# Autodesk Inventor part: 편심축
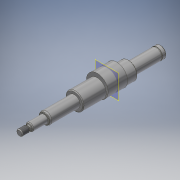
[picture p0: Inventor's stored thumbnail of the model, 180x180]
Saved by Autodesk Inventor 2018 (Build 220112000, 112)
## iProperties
Created: 2015-09
Part Number: 편심축
Material: 강철, 연강
Document SubType Name: Modeling
Designer: mduedu
Density: 1 g/cm^3
Appearance: 강철
Author: mduedu
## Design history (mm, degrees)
sketch "스케치1"
  geometry: L1 (-91, 0)-(91, 0); L2 (-91, 0)-(-91, 7.5); L3 (-91, 7.5)-(-49.85, 7.5); L4 (-49.85, 7.5)-(-49.85, 11.5); L5 (-49.85, 11.5)-(20.15, 11.5); L6 (20.15, 11.5)-(20.15, 7.5); L7 (20.15, 7.5)-(59.15, 7.5); L8 (59.15, 7.5)-(59.15, 5); L9 (59.15, 5)-(78.15, 5); L10 (78.15, 5)-(78.15, 3); L11 (78.15, 3)-(80.15, 3); L12 (81.882, 4)-(91, 4); L13 (91, 4)-(91, 0); L14 (80.15, 3)-(81.882, 4); 2 further points
  constraints: 28 end point, 9 parallel, 2 perpendicular, 1 coincident, 1 collinear, 1 horizontal, 1 midpoint
  dimensions: "d0" = 41.15 distance of L2.end L3.end; "d2" = 70 distance of L4.end L5.end; "d3" = 39 distance of L6.end L7.end; "d4" = 182 distance of L1.start L1.end; "d5" = 19 distance of L8.end L9.end; "d7" = 8 diameter of L12 L1; "d8" = 6 diameter of L11 L1; "d9" = 10 diameter of L9 L1; "d10" = 15 diameter of L7 L1; "d11" = 23 diameter of L5 L1; "d12" = 15 diameter of L3 L1; "d40" = 30 deg angle of L14 L12; "d41" = 2 distance of L10.end L11.end; "d42" = 3.73205 horizontal distance of L12.start L10.end (derived)
revolve "회전1" sketch "스케치1" stored, may be unused: angle "d13" = 90 deg
fillet "모깎기1" dims "d43" = 0.6
sketch "스케치2"
  geometry: L1 (-91, 7.5)-(-49.85, 7.5) reference; L2 (-91, -7.5)-(-91, 7.5) reference; L3 (91, -4)-(91, 4) reference; L4 (-91, 0)-(91, 0); L5 (-86, 7.5)-(-84.85, 7.5); L6 (-84.85, 7.5)-(-84.85, 7.15); L7 (-84.85, 7.15)-(-86, 7.15); L8 (-86, 7.15)-(-86, 7.5); 1 further point
  constraints: 10 end point, 2 midpoint, 2 parallel, 1 horizontal, 1 perpendicular, 1 point on line
  dimensions: "d14" = 5 distance between parallel lines of L8 L2; "d15" = 14.3 diameter of L7 L4; "d16" = 1.15 distance of L6.end L7.end
revolve "회전2" sketch "스케치2" stored, may be unused: angle "d17" = 90 deg
node "작업 평면1"
sketch "스케치3"
  geometry: C1 r 11.5 at (0, 0) reference; C2 r 14 at (0, 2.5); 1 further point
  constraints: 1 centre point, 1 tangent, 1 vertical alignment
  dimensions: "d19" = 28 diameter of C2
extrude "돌출1" join sketch "스케치3" distance "d21" = 25; taper "d22" = 0 deg
node "작업 평면2"
sketch "스케치4"
  geometry: L1 (9.5, 7.5)-(9.5, -7.5) reference; L2 (-9.5, 5)-(-9.5, -5) reference; L3 (9.5, 0)-(-9.5, 0); L4 (-5, -1.5)-(4, -1.5); L5 (4, 1.5)-(-5, 1.5); A1 r 1.5 centre (4, 0) between (4, -1.5) and (4, 1.5); A2 r 1.5 centre (-5, 0) between (-5, 1.5) and (-5, -1.5); 1 further point
  constraints: 6 end point, 4 point on circle, 4 tangent, 2 centre point, 2 midpoint, 2 parallel, 1 point on line
  dimensions: "d23" = 3 distance between parallel lines of L5 L4; "d25" = 12 dimension on A2 A1; "d26" = 3 distance edge to line of A2 L2
extrude "돌출2" cut sketch "스케치4" distance "d27" = 1.8; taper "d28" = 0 deg
chamfer "모따기1" distance "d29" = 1; stored, may be unused: second distance "d30" = 2, angle "d31" = 45 deg
sketch "스케치5"
  geometry: L1 (80.289, 3.08)-(81.882, 4) reference; L2 (81.882, 4)-(91, 4) reference; L3 (91, 4)-(91, -4) reference; L4 (91, -4)-(81.882, -4) reference; L5 (81.882, -4)-(80.289, -3.08) reference; L6 (79.989, -3)-(78.75, -3) reference; L7 (78.15, -3.6)-(78.15, -5) reference; L8 (78.15, -5)-(75.15, -5) reference; L9 (75.15, -5)-(75.15, -3.2) reference; L10 (75.15, -3.2)-(63.15, -3.2) reference; L11 (63.15, -3.2)-(63.15, -5) reference; L12 (63.15, -5)-(59.15, -5) reference; L13 (59.15, -5)-(59.15, -7.5) reference; L14 (59.15, -7.5)-(20.15, -7.5) reference; L15 (20.15, -7.5)-(20.15, -10.5) reference; L16 (20.15, -10.5)-(19.15, -11.5) reference; L17 (19.15, -11.5)-(-9.35, -11.5) reference; L18 (-9.35, -11.5)-(-34.35, -11.5) reference; L19 (-34.35, -11.5)-(-48.85, -11.5) reference; L20 (-48.85, -11.5)-(-49.85, -10.5) reference; L21 (-49.85, -10.5)-(-49.85, -7.5) reference; L22 (-49.85, -7.5)-(-84.85, -7.5) reference; L23 (-84.85, -7.5)-(-84.85, -7.15) reference; L24 (-84.85, -7.15)-(-86, -7.15) reference; L25 (-86, -7.15)-(-86, -7.5) reference; L26 (-86, -7.5)-(-90, -7.5) reference; L27 (-90, -7.5)-(-91, -6.5) reference; L28 (-91, -6.5)-(-91, 6.5) reference; L29 (-91, 6.5)-(-90, 7.5) reference; L30 (-90, 7.5)-(-86, 7.5) reference; L31 (-86, 7.5)-(-86, 7.15) reference; L32 (-86, 7.15)-(-84.85, 7.15) reference; L33 (-84.85, 7.15)-(-84.85, 7.5) reference; L34 (-84.85, 7.5)-(-49.85, 7.5) reference; L35 (-49.85, 7.5)-(-49.85, 10.5) reference; L36 (-49.85, 10.5)-(-48.85, 11.5) reference; L37 (-48.85, 11.5)-(-34.35, 11.5) reference; L38 (-34.35, 11.5)-(-34.35, 16.5) reference; L39 (-34.35, 16.5)-(-9.35, 16.5) reference; L40 (-9.35, 16.5)-(-9.35, 11.5) reference; L41 (-9.35, 11.5)-(19.15, 11.5) reference; L42 (19.15, 11.5)-(20.15, 10.5) reference; L43 (20.15, 10.5)-(20.15, 7.5) reference; L44 (20.15, 7.5)-(59.15, 7.5) reference; L45 (59.15, 7.5)-(59.15, 5) reference; L46 (59.15, 5)-(78.15, 5) reference; L47 (78.15, 5)-(78.15, 3.6) reference; L48 (78.75, 3)-(79.989, 3) reference; L49 (0, 0)-(91, 0); L50 (59.15, -6.55)-(57.505, -7.5); L51 (57.505, -7.5)-(59.15, -7.5); L52 (59.15, -7.5)-(59.15, -6.55); A1 r 0.6 centre (79.989, 3.6) between (79.989, 3) and (80.289, 3.08) reference; A2 r 0.6 centre (79.989, -3.6) between (80.289, -3.08) and (79.989, -3) reference; A3 r 0.6 centre (78.75, -3.6) between (78.75, -3) and (78.15, -3.6) reference; A4 r 0.6 centre (78.75, 3.6) between (78.15, 3.6) and (78.75, 3) reference
  constraints: 8 end point, 2 point on line, 1 midpoint, 1 parallel, 1 perpendicular
  dimensions: "d44" = 30 deg angle of L50 L51; "d45" = 13.1 diameter of L50.start L49
revolve "회전3" sketch "스케치5" stored, may be unused: angle "d46" = 90 deg
fillet "모깎기2" dims "d47" = 4, "d48" = 0.5
feature "스레드1" dims "d32" = 10, "d33" = 0
chamfer "모따기2" distance "d34" = 1; stored, may be unused: second distance "d35" = 2, angle "d36" = 45 deg
chamfer "모따기3" distance "d37" = 1; stored, may be unused: second distance "d38" = 2, angle "d39" = 45 deg
node "작업 평면3"
node "작업 평면4"
sketch "스케치6"
  geometry: L1 (14, 0)-(-14, 0); A1 r 14 centre (0, 0) between (0, -14) and (14, 0) reference; 1 further point
  constraints: 2 end point, 2 point on circle, 1 horizontal
node "솔리드1"
node "절단 모서리 투영1"
other parameters: "d18" = -29.5
